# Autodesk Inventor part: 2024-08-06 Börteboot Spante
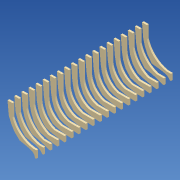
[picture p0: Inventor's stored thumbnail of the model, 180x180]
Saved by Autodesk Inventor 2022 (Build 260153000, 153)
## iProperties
Created: 2024-08
Part Number: 2024-08-06 Börteboot Spante
Material: Generisch
Document SubType Name: Modeling
Designer: i3meg
Density: 1 g/cm^3
Appearance: Beige
Author: i3meg
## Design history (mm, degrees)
sketch "Skizze3"
  geometry: L1 (-117.6, 0)-(19.6, 0) reference; L2 (0, -36.667)-(0, 220.005) reference; L3 (-4, 12)-(-4, 0); L4 (0, 0)-(0, 30); L5 (-35, 30)-(0, 30); L6 (-62, 23)-(-78, 41); L7 (-78, 41)-(-86, 62); L8 (-86, 62)-(-90, 84); L9 (-90, 130)-(-78, 130); L10 (-90, 84)-(-90, 130); L11 (-98, 115)-(-98, 105); L12 (-98, 105)-(-90, 105); L13 (-98, 115)-(-78, 115); L14 (-78, 130)-(-78, 90); L15 (-4, 0)-(0, 0); L16 (-4, 12)-(0, 12); L17 (-90, 84)-(-94, 130); L18 (-94, 130)-(-90, 130); A1 r 59.222 centre (-18.855, 86.979) between (-78, 90) and (-35, 30); A2 r 171.355 centre (-1.548, 183.337) between (-62, 23) and (-4, 12)
  constraints: 34 end point, 5 point on line, 4 perpendicular, 4 point on circle, 3 vertical, 2 centre point, 2 horizontal
  dimensions: "d283" = 4 distance between parallel lines of L2 L3; "d514" = 90 distance from line of L2 L8.end; "d519" = 130 distance from line of L1 L9.start; "d527" = 12 distance of L9.start L9.end; "d538" = 10 distance of L11.start L11.end; "d545" = 35 distance from line of L2 L5.start; "d1132" = 15 distance between parallel lines of L9 L13; "d1133" = 40 distance of L9.end L14.end; "d1134" = 8 distance between parallel lines of L10 L11; "d1144" = 86 distance from line of L2 L7.end; "d1145" = 78 distance from line of L2 L6.end; "d1146" = 62 distance from line of L2 L6.start; "d1245" = 22 vertical distance of L8.end L7.end; "d1246" = 21 vertical distance of L7.end L6.end; "d1247" = 18 vertical distance of L6.end L6.start; "d1452" = 4 distance of L9.start L17.end; "d2194" = 46 distance of L9.start L8.end
extrude "Extrusion11" new body sketch "Skizze3" stored distance "d616" = 6; taper "d617" = 0 deg
pattern_linear "Rechteckige Anordnung3" dims "d675" = 23
workplane "Arbeitsebene5"
sketch "Skizze25"
  geometry: L1 (-62, -6)-(-78, 12); L2 (-78, 12)-(-86, 33); L3 (-35, 0)-(0, 0); L4 (-86, 33)-(-90, 54); L5 (-98, 75)-(-90, 75); L6 (-98, 85)-(-98, 75); L7 (-98, 85)-(-82, 85); L8 (-90, 100)-(-78, 100); L9 (-90, 54)-(-90, 100); L10 (-78, 100)-(-78, 60); L11 (-4, -18)-(-4, -30); L12 (-4, -30)-(0, -30); L13 (0, -30)-(0, 0); L14 (-4, -18)-(0, -18); L15 (-122.269, -30)-(47.614, -30) reference; L16 (0, -88.067)-(0, 318.403) reference; L17 (-90, 54)-(-94, 100); L18 (-94, 100)-(-90, 100); A1 r 66.906 centre (-11.141, 62.507) between (-78, 60) and (-35, 0); A2 r 279.676 centre (23.345, 260.336) between (-62, -6) and (-4, -18)
  constraints: 34 end point, 4 point on circle, 4 point on line, 3 vertical, 2 centre point, 2 horizontal, 2 perpendicular
  dimensions: "d1150" = 12 distance of L8.start L8.end; "d1151" = 10 distance of L6.start L5.start; "d1152" = 15 distance between parallel lines of L8 L7; "d1153" = 40 distance of L8.end L10.end; "d1154" = 8 distance between parallel lines of L9 L6; "d1157" = 78 distance from line of L16 L1.end; "d1158" = 86 distance from line of L16 L2.end; "d1159" = 90 distance from line of L16 L4.end; "d1160" = 4 distance between parallel lines of L13 L11; "d1161" = 30 distance between parallel lines of L15 L3; "d1162" = 18 distance between parallel lines of L14 L3; "d1165" = 84 distance from line of L15 L4.end; "d1239" = 35 distance from line of L13 L3.start; "d1241" = 21 vertical distance of L2.end L4.end; "d1242" = 21 vertical distance of L2.end L1.end; "d1243" = 18 vertical distance of L1.start L1.end; "d1244" = 130 distance between parallel lines of L15 L8; "d1453" = 4 distance of L17.end L8.start; "d2116" = 62 distance from line of L16 L1.start
extrude "Extrusion24" join sketch "Skizze25" distance "d1163" = 6; taper "d1164" = 0 deg
workplane "Arbeitsebene14"
sketch "Skizze26"
  geometry: L1 (-86, 34)-(-90, 55); L2 (-78, 14)-(-86, 34); L3 (-62, -4)-(-78, 14); L4 (-30, 0)-(0, 0); L5 (-98, 85)-(-98, 75); L6 (-4, -18)-(0, -18); L7 (-4, -18)-(-4, -30); L8 (-4, -30)-(0, -30); L9 (0, -30)-(0, 0); L10 (-90, 100)-(-78, 100); L11 (-78, 100)-(-78, 60); L12 (-90, 55)-(-90, 100); L13 (-98, 75)-(-90, 75); L14 (-98, 85)-(-82, 85); L15 (-131.301, -30)-(101.804, -30) reference; L16 (0, -117.903)-(0, 497.417) reference; L17 (-90, 55)-(-94, 100); L18 (-94, 100)-(-90, 100); A1 r 433.619 centre (68.503, 409.514) between (-62, -4) and (-4, -18); A2 r 81.932 centre (2.509, 75.207) between (-78, 60) and (-30, 0)
  constraints: 34 end point, 4 point on circle, 4 point on line, 3 vertical, 2 centre point, 2 horizontal, 2 perpendicular
  dimensions: "d1170" = 12 distance of L10.start L10.end; "d1171" = 10 distance of L5.start L5.end; "d1172" = 15 distance between parallel lines of L10 L14; "d1173" = 40 distance of L10.end L11.end; "d1174" = 8 distance between parallel lines of L12 L5; "d1176" = 4 distance between parallel lines of L9 L7; "d1177" = 18 distance between parallel lines of L6 L4; "d1178" = 30 distance from line of L15 L4.end; "d1180" = 78 distance from line of L16 L2.start; "d1181" = 86 distance from line of L16 L1.start; "d1182" = 90 distance from line of L16 L1.end; "d1183" = 130 distance between parallel lines of L15 L10; "d1185" = 30 distance of L4.start L4.end; "d1186" = 45 distance of L10.start L1.end; "d1248" = 21 vertical distance of L1.end L1.start; "d1249" = 20 vertical distance of L2.start L1.start; "d1250" = 18 vertical distance of L3.start L2.start; "d1251" = 62 distance from line of L16 L3.start; "d1454" = 4 distance of L17.end L10.start
extrude "Extrusion25" join sketch "Skizze26" distance "d1190" = 6; taper "d1191" = 0 deg
workplane "Arbeitsebene17"
sketch "Skizze30"
  geometry: L1 (-86, 36)-(-90, 56); L2 (-77, 16)-(-86, 36); L3 (-62, -2)-(-77, 16); L4 (-24, 1)-(0, 1); L5 (-98, 85)-(-98, 75); L6 (-4, -18)-(0, -18); L7 (-4, -18)-(-4, -30); L8 (-4, -30)-(0, -30); L9 (0, -30)-(0, 1); L10 (-90, 100)-(-78, 100); L11 (-78, 100)-(-78, 60); L12 (-90, 56)-(-90, 100); L13 (-98, 75)-(-90, 75); L14 (-98, 85)-(-82, 85); L15 (-117.95, -30)-(21.701, -30) reference; L16 (0, -283.862)-(0, 163.977) reference; L17 (-90, 56)-(-94, 100); L18 (-94, 100)-(-90, 100); A1 r 81.932 centre (1.751, 78.781) between (-78, 60) and (-24, 1); A2 r 219.794 centre (-90.899, -219.885) between (-4, -18) and (-62, -2)
  constraints: 34 end point, 4 point on circle, 3 vertical, 2 centre point, 2 perpendicular, 2 point on line, 1 horizontal
  dimensions: "d1279" = 12 distance of L10.start L10.end; "d1280" = 10 distance of L5.start L5.end; "d1281" = 15 distance between parallel lines of L10 L14; "d1282" = 40 distance of L10.end L11.end; "d1283" = 8 distance between parallel lines of L12 L5; "d1284" = 4 distance between parallel lines of L9 L7; "d1285" = 19 distance between parallel lines of L6 L4; "d1291" = 24 distance of L4.start L4.end; "d1292" = 44 distance of L10.start L1.end; "d1293" = 20 vertical distance of L1.end L1.start; "d1294" = 20 vertical distance of L2.start L1.start; "d1295" = 18 vertical distance of L3.start L2.start; "d1298" = 130 distance between parallel lines of L15 L10; "d1345" = 90 distance between parallel lines of L16 L12; "d1346" = 31 distance between parallel lines of L15 L4; "d1423" = 62 distance from line of L16 L3.start; "d1455" = 4 distance of L17.end L10.start; "d1475" = 86 distance from line of L16 L1.start; "d2117" = 77 distance from line of L16 L2.start
extrude "Extrusion30" join sketch "Skizze30" distance "d1300" = 6; taper "d1301" = 0 deg
workplane "Arbeitsebene18"
sketch "Skizze31"
  geometry: L1 (-85, 38)-(-90, 58); L2 (-76, 18)-(-85, 38); L3 (-62, 0)-(-76, 18); L4 (-15, 2)-(0, 2); L5 (-98, 85)-(-98, 75); L6 (-4, -18)-(0, -18); L7 (-4, -18)-(-4, -30); L8 (-4, -30)-(0, -30); L9 (0, -30)-(0, 2); L10 (-90, 100)-(-78, 100); L11 (-78, 100)-(-78, 60); L12 (-90, 58)-(-90, 100); L13 (-98, 75)-(-90, 75); L14 (-98, 85)-(-82, 85); L15 (-117.763, -30)-(20.576, -30) reference; L16 (0, -56)-(0, 126) reference; L17 (-62, 0)-(-33.474, -4); L18 (-33.474, -4)-(-10, -4); L19 (-10, -4)-(-4, -18); L20 (-90, 58)-(-94, 100); L21 (-94, 100)-(-90, 100); A1 r 81.932 centre (0.813, 82.392) between (-78, 60) and (-15, 2)
  constraints: 34 end point, 3 vertical, 2 horizontal, 2 perpendicular, 2 point on circle, 2 point on line, 1 centre point, 3 other
  dimensions: "d1303" = 12 distance of L10.start L10.end; "d1304" = 10 distance of L5.start L5.end; "d1305" = 15 distance between parallel lines of L10 L14; "d1306" = 40 distance of L10.end L11.end; "d1307" = 8 distance between parallel lines of L12 L5; "d1308" = 4 distance between parallel lines of L9 L7; "d1309" = 20 distance between parallel lines of L6 L4; "d1311" = 42 distance of L10.start L1.end; "d1318" = 90 distance between parallel lines of L16 L12; "d1319" = 32 distance between parallel lines of L15 L4; "d1320" = 130 distance between parallel lines of L15 L10; "d1421" = 10 distance from line of L16 L18.end; "d1422" = 26 distance from line of L15 L18.end; "d1458" = 4 distance of L20.end L10.start; "d1471" = 20 vertical distance of L2.start L1.start; "d1472" = 20 vertical distance of L1.start L1.end; "d1473" = 18 vertical distance of L2.start L3.start; "d2101" = 85 distance from line of L16 L1.start; "d2114" = 62 distance from line of L16 L3.start; "d2115" = 76 distance from line of L16 L2.start
extrude "Extrusion31" join sketch "Skizze31" distance "d1321" = 6; taper "d1322" = 0 deg
workplane "Arbeitsebene26"
sketch "Skizze43"
  geometry: L1 (-26.579, -7)-(-43, 12); L2 (-43, 12)-(-50.5, 33); L3 (0, 0)-(35, 0); L4 (-50.5, 33)-(-55, 54); L5 (-63, 75)-(-55, 75); L6 (-63, 85)-(-63, 75); L7 (-63, 85)-(-47, 85); L8 (-55, 100)-(-43, 100); L9 (-55, 54)-(-55, 100); L10 (-43, 100)-(-43, 60); L11 (31, -18)-(31, -30); L12 (31, -30)-(35, -30); L13 (35, -30)-(35, 0); L14 (31, -18)-(35, -18); L15 (-55, 54)-(-59, 100); L16 (-59, 100)-(-55, 100); L17 (-86.48, -30)-(77.882, -30) reference; L18 (35, -88.139)-(35, 318.834) reference; A1 r 66.906 centre (23.859, 62.507) between (-43, 60) and (0, 0); A2 r 279.676 centre (54.402, 260.695) between (-26.579, -7) and (31, -18); 1 further point
  constraints: 34 end point, 4 point on circle, 3 point on line, 3 vertical, 2 centre point, 2 horizontal, 2 perpendicular
  dimensions: "d1538" = 12 distance of L8.start L8.end; "d1539" = 10 distance of L6.start L5.start; "d1540" = 15 distance between parallel lines of L8 L7; "d1541" = 40 distance of L8.end L10.end; "d1542" = 8 distance between parallel lines of L9 L6; "d1546" = 4 distance between parallel lines of L13 L11; "d1548" = 18 distance between parallel lines of L14 L3; "d1550" = 35 distance from line of L13 L3.start; "d1551" = 21 vertical distance of L2.end L4.end; "d1552" = 21 vertical distance of L2.end L1.end; "d1553" = 19 vertical distance of L1.start L1.end; "d1555" = 4 distance of L15.end L8.start; "d2103" = 90 distance between parallel lines of L18 L9; "d2104" = 85.5 distance from line of L18 L2.end; "d2119" = 78 distance from line of L18 L1.end
extrude "Extrusion41" join sketch "Skizze43" distance "d1556" = 6; taper "d1557" = 0 deg
workplane "Arbeitsebene27"
sketch "Skizze44"
  geometry: L1 (-50, 34)-(-55, 55); L2 (-42, 14)-(-50, 34); L3 (-26, -5)-(-42, 14); L4 (5, 0)-(35, 0); L5 (-63, 85)-(-63, 75); L6 (31, -18)-(35, -18); L7 (31, -18)-(31, -30); L8 (31, -30)-(35, -30); L9 (35, -30)-(35, 0); L10 (-55, 100)-(-43, 100); L11 (-43, 100)-(-43, 60); L12 (-55, 55)-(-55, 100); L13 (-63, 75)-(-55, 75); L14 (-63, 85)-(-47, 85); L15 (-55, 55)-(-59, 100); L16 (-59, 100)-(-55, 100); L17 (-95.34, -30)-(131.04, -30) reference; L18 (35, -118.06)-(35, 498.362) reference; A1 r 433.619 centre (98.7, 410.301) between (-26, -5) and (31, -18); A2 r 81.932 centre (37.509, 75.207) between (-43, 60) and (5, 0); 1 further point
  constraints: 34 end point, 4 point on circle, 3 vertical, 2 centre point, 2 horizontal, 2 perpendicular, 2 point on line
  dimensions: "d1559" = 12 distance of L10.start L10.end; "d1560" = 10 distance of L5.start L5.end; "d1561" = 15 distance between parallel lines of L10 L14; "d1562" = 40 distance of L10.end L11.end; "d1563" = 8 distance between parallel lines of L12 L5; "d1564" = 4 distance between parallel lines of L9 L7; "d1565" = 18 distance between parallel lines of L6 L4; "d1571" = 30 distance of L4.start L4.end; "d1572" = 45 distance of L10.start L1.end; "d1573" = 21 vertical distance of L1.end L1.start; "d1574" = 20 vertical distance of L2.start L1.start; "d1575" = 19 vertical distance of L3.start L2.start; "d1577" = 4 distance of L15.end L10.start; "d2105" = 90 distance between parallel lines of L18 L12; "d2106" = 85 distance from line of L18 L1.start; "d2120" = 77 distance from line of L18 L2.start
extrude "Extrusion42" join sketch "Skizze44" distance "d1578" = 6; taper "d1579" = 0 deg
workplane "Arbeitsebene28"
sketch "Skizze49"
  geometry: L1 (-49.5, 36)-(-55, 56); L2 (-40, 16)-(-49.5, 36); L3 (-25, -2)-(-40, 16); L4 (10.838, 0)-(34.838, 0); L5 (-63, 85)-(-63, 75); L6 (30.838, -18)-(34.838, -18); L7 (30.838, -18)-(30.838, -31); L8 (30.838, -31)-(34.838, -31); L9 (34.838, -31)-(34.838, 0); L10 (-55, 100)-(-43, 100); L11 (-43, 100)-(-43, 60); L12 (-55, 56)-(-55, 100); L13 (-63, 75)-(-55, 75); L14 (-63, 85)-(-47, 85); L15 (-55, 56)-(-59, 100); L16 (-59, 100)-(-55, 100); L17 (35, -283.325)-(35, 163.888) reference; A1 r 81.932 centre (37.011, 77.639) between (-43, 60) and (10.838, 0); A2 r 219.794 centre (-57.094, -219.438) between (30.838, -18) and (-25, -2); 3 further points; 1 other entity
  constraints: 34 end point, 4 point on circle, 3 vertical, 2 centre point, 2 perpendicular, 2 point on line, 1 horizontal, 1 other
  dimensions: "d1658" = 12 distance of L10.start L10.end; "d1659" = 10 distance of L5.start L5.end; "d1660" = 15 distance between parallel lines of L10 L14; "d1661" = 40 distance of L10.end L11.end; "d1662" = 8 distance between parallel lines of L12 L5; "d1663" = 4 distance between parallel lines of L9 L7; "d1664" = 18 distance between parallel lines of L6 L4; "d1665" = 24 distance of L4.start L4.end; "d1666" = 44 distance of L10.start L1.end; "d1667" = 20 vertical distance of L1.end L1.start; "d1668" = 20 vertical distance of L2.start L1.start; "d1669" = 18 vertical distance of L3.start L2.start; "d1674" = 4 distance of L15.end L10.start; "d2107" = 90 distance between parallel lines of L17 L12; "d2108" = 84.5 distance from line of L17 L1.start; "d2121" = 75 distance from line of L17 L2.start
extrude "Extrusion46" join sketch "Skizze49" distance "d1676" = 6; taper "d1677" = 0 deg
workplane "Arbeitsebene31"
sketch "Skizze51" dims "d1738" = 0
  geometry: L1 (-48, 38)-(-55, 57); L2 (-38, 19)-(-48, 38); L3 (-23, 3)-(-38, 19); L4 (20, 2)-(35, 2); L5 (-63, 85)-(-63, 75); L6 (31, -18)-(35, -18); L7 (31, -18)-(31, -30); L8 (31, -30)-(35, -30); L9 (35, -30)-(35, 2); L10 (-55, 100)-(-43, 100); L11 (-43, 100)-(-43, 60); L12 (-55, 57)-(-55, 100); L13 (-63, 75)-(-55, 75); L14 (-63, 85)-(-47, 85); L15 (-23, 3)-(1.526, -1); L16 (1.526, -1)-(25, -4); L17 (25, -4)-(31, -18); L18 (-55, 57)-(-59, 100); L19 (-59, 100)-(-55, 100); L20 (-82.763, -30)-(55.576, -30) reference; L21 (35, -56)-(35, 126) reference; A1 r 81.932 centre (35.813, 82.392) between (-43, 60) and (20, 2); 1 further point
  constraints: 34 end point, 3 vertical, 2 horizontal, 2 perpendicular, 2 point on circle, 2 point on line, 1 centre point, 3 other
  dimensions: "d1697" = 12 distance of L10.start L10.end; "d1698" = 10 distance of L5.start L5.end; "d1699" = 15 distance between parallel lines of L10 L14; "d1700" = 40 distance of L10.end L11.end; "d1701" = 8 distance between parallel lines of L12 L5; "d1702" = 4 distance between parallel lines of L9 L7; "d1703" = 20 distance between parallel lines of L6 L4; "d1704" = 43 distance of L10.start L1.end; "d1710" = 4 distance of L18.end L10.start; "d1711" = 19 vertical distance of L2.start L1.start; "d1712" = 19 vertical distance of L1.start L1.end; "d1713" = 16 vertical distance of L2.start L3.start; "d2109" = 90 distance between parallel lines of L21 L12; "d2110" = 83 distance from line of L21 L1.start; "d2122" = 73 distance from line of L21 L2.start
extrude "Extrusion47" join sketch "Skizze51" distance "d1714" = 6; taper "d1715" = 0 deg
workplane "Arbeitsebene32"
sketch "Skizze52"
  geometry: L1 (-46, 40)-(-54, 59); L2 (-35, 22)-(-46, 40); L3 (-19, 7)-(-35, 22); L4 (25, 6)-(35, 6); L5 (-62, 85)-(-62, 75); L6 (31, -18)-(35, -18); L7 (31, -18)-(31, -30); L8 (31, -30)-(35, -30); L9 (35, -30)-(35, 6); L10 (-54, 100)-(-42, 100); L11 (-42, 100)-(-42, 60); L12 (-54, 59)-(-54, 100); L13 (-62, 75)-(-54, 75); L14 (-62, 85)-(-46, 85); L15 (-19, 7)-(23, -2.108); L16 (23, -2.108)-(28, -2); L17 (28, -2)-(31, -18); L18 (-54, 59)-(-58, 100); L19 (-58, 100)-(-54, 100); L20 (-81.497, -30)-(54.983, -30) reference; L21 (35, -56)-(35, 126) reference; A1 r 81.932 centre (35.255, 87.288) between (-42, 60) and (25, 6)
  constraints: 35 end point, 3 vertical, 2 horizontal, 2 perpendicular, 2 point on circle, 2 point on line, 1 centre point, 3 other
  dimensions: "d1717" = 12 distance of L10.start L10.end; "d1718" = 10 distance of L5.start L5.end; "d1719" = 15 distance between parallel lines of L10 L14; "d1720" = 40 distance of L10.end L11.end; "d1721" = 8 distance between parallel lines of L12 L5; "d1722" = 4 distance between parallel lines of L9 L7; "d1723" = 24 distance between parallel lines of L6 L4; "d1724" = 10 distance of L4.start L4.end; "d1725" = 41 distance of L10.start L1.end; "d1728" = 7 distance from line of L9 L16.end; "d1732" = 19 vertical distance of L1.start L1.end; "d1733" = 18 vertical distance of L2.start L1.start; "d1734" = 15 vertical distance of L3.start L2.start; "d1736" = 4 distance of L18.end L10.start; "d2111" = 89 distance between parallel lines of L21 L12; "d2112" = 81 distance from line of L21 L1.start; "d2123" = 70 distance from line of L21 L2.start; "d2192" = 36 distance between parallel lines of L20 L4
extrude "Extrusion48" join sketch "Skizze52" distance "d1737" = 6; taper "d1738" = 0 deg
node "Volumenkörper7"
other parameters: "d736" = 23, "d1166" = 23, "d1253" = 23, "d1302" = 23, "d1537" = 23, "d1558" = 23, "d1580" = 23, "d1696" = 23, "d1716" = 23, "d2096" = 3, "d2097" = 3, "d2098" = 3
